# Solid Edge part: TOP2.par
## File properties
Author: Andrea Rangi V
Template: Ansi Metric part.par
Last saved by: Andrea Rangi V
Revision: 4
Application: Solid Edge
Accuracy: 0.990
Username: Andrea Rangi V
Face Style: Model Default
Coef. of Thermal Exp: 0.0
Thermal Conductivity: 0.0
Specific Heat: 0.0
Modulus of Elasticity: 0.0
Poisson's Ratio: 0.0
Yield Stress: 0.0
Ultimate Stress: 0.0
Elongation: 0.0
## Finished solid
Body 1: solid body, 72 faces, 210 edges, 140 vertices.
  Faces by surface: plane 72
  Edges by curve: line 210
Bounding box of the edges (mm): 180.000 x 3.000 x 270.000, from (-84.555, 0, -135) to (95.445, 3, 135).
Planar faces by outward normal: +x 17, +y 1, +z 17, -x 18, -y 1, -z 18
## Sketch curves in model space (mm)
line (95.445, 0, 135) -> (75.445, 0, 135)
line (-74.555, 0, 135) -> (-64.555, 0, 135)
line (-54.555, 0, -135) -> (-34.555, 0, -135)
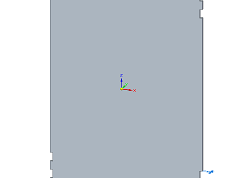
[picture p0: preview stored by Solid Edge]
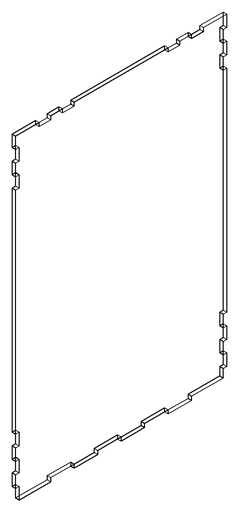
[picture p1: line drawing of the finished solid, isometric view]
